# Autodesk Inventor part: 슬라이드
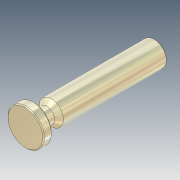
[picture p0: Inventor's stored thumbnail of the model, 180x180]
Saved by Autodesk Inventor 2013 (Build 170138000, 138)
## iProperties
Company: 한국ATC센터
Created: 2014-10
Part Number: 슬라이드
Document SubType Name: Modeling
Designer: 한국ATC센터
Density: 7.86 g/cm^3
Material: 강, 연강
Mass: 735.303 g
Surface Area: 161.098 cm^2
Volume: 93.55 cm^3
Author: KYOUNG IL JANG
Revision Number: 1
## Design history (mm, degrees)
sketch "스케치1"
  geometry: L1 (-14, 195)-(-14, 171) reference; L2 (19, 106.5)-(-19, 106.5) reference; L3 (0, 106.5)-(0, 256.5); L4 (0, 256.5)-(-14, 256.5); L5 (-14, 256.5)-(-14, 136.5); L6 (-14, 116.5)-(-21, 116.5); L7 (-21, 116.5)-(-21, 106.5); L8 (-21, 106.5)-(0, 106.5); L9 (-14, 116.5)-(-9, 116.5); L10 (-9, 116.5)-(-9, 131.5); L11 (-9, 131.5)-(-14, 136.5); L12 (-14, 136.5)-(-14, 116.5); 1 further point
  constraints: 24 end point, 5 perpendicular, 3 parallel, 1 collinear, 1 horizontal, 1 midpoint, 1 point on line, 1 vertical, 4 other
  dimensions: "d0" = 10 distance between parallel lines of L6 L8; "d1" = 42 diameter of L7 L3; "d2" = 150 distance of L3.start L3.end; "d3" = 135 deg angle of L11 L5; "d4" = 18 diameter of L10 L3; "d5" = 30 distance from line of L5.end L8
revolve "회전1" sketch "스케치1" stored, may be unused: angle "d6" = 90 deg
chamfer "모따기1" distance "d7" = 1; stored, may be unused: second distance "d8" = 2, angle "d9" = 45 deg
fillet "모깎기1" dims "d10" = 2
node "솔리드1"
